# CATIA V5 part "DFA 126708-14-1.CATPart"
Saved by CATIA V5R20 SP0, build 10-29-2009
Part number: DFA 126708-14-1
Revision: ANY
Definition: UNKNOWN
Nomenclature: DFA 126708-14-1
Source: Unknown
Bounding box of the stored display mesh (mm): x -5.85 to 5.85, y -8 to 12.1, z -6 to 6
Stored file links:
  C:\Users\Utente\Desktop\IO LAVORO\3D X SITO CF\CUMSA\3D files FA\FA 126708-21\DFA 126708-14-1.CATPart
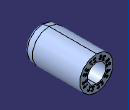
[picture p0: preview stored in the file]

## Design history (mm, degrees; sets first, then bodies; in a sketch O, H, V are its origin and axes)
Body1 "Cortar-Extruir5" (main body)
  Solid1: solid without history
Body2 "Saliente-Extruir1"
  Solid2: solid without history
